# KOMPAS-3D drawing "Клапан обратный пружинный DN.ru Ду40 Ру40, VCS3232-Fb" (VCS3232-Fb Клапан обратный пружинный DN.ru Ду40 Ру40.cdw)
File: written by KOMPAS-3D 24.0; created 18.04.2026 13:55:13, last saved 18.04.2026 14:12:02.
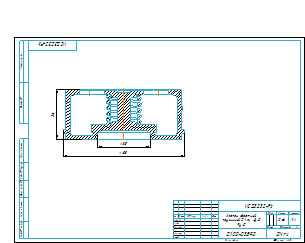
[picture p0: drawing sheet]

Document properties: c3d_UniqueCompID: 071bd168-1a06-425c-849c-e99e84a96128; Наименование: Деталь; Автор: 712; Класс точности: c; Знак неуказанной шероховатости: Шероховатость не задана; Рассекать на разрезах: Да; c3d_UniqueCompID: 071bd168-1a06-425c-849c-e99e84a96128; Наименование: Деталь; Автор: 712; Класс точности: c; Знак неуказанной шероховатости: Шероховатость не задана; Рассекать на разрезах: Да; c3d_UniqueCompID: 071bd168-1a06-425c-849c-e99e84a96128; Наименование: Деталь; Автор: 712; Класс точности: c; Знак неуказанной шероховатости: Шероховатость не задана; Рассекать на разрезах: Да; c3d_UniqueCompID: 071bd168-1a06-425c-849c-e99e84a96128; Наименование: Деталь; Автор: 712; Класс точности: c; Знак неуказанной шероховатости: Шероховатость не задана; Рассекать на разрезах: Да; c3d_UniqueCompID: 071bd168-1a06-425c-849c-e99e84a96128; Наименование: Деталь; Автор: 712; Класс точности: c; Знак неуказанной шероховатости: Шероховатость не задана; Рассекать на разрезах: Да; Автор: 712; Форматы листов документа: A3; Полное имя файла: VCS3232-Fb Клапан обратный пружинный DN.ru Ду40 Ру40.m3d; Масса: 0.61; Наименование: Клапан обратный пружинный DN.ru Ду40 Ру40; Количество листов документа: 1; Примечание: D100-03890

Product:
- Body: Тело 1  | qty 1
    Масса: 0.509779
- Part/product: Клапан обратный пружинный DN.ru Ду40 Ру40  | designation VCS3232-Fb
    Масса: 0.61
    Раздел спецификации: Прочие изделия
    Примечание: D100-03890
    additional columns: 071bd168-1a06-425c-849c-e99e84a96128; Деталь; 712; c; Шероховатость не задана; Да

Views: Вид 1, Местный разрез 1, Спереди
Referenced files in C:\Users\712\Desktop\Новая папка (4)\: VCS3232-Fb Клапан обратный пружинный DN.ru Ду15 Ру40.m3d, VCS3232-Fb Клапан обратный пружинный DN.ru Ду40 Ру40.m3d, VCS3232-Fb Клапан обратный пружинный DN.ru Ду15 Ру40.cdw
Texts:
  VCS3232-Fb
  Клапан обратный
  пружинный DN.ru Ду40
  Ру40
  Клапан обратный пружинный DN.ru Ду40 Ру40
  VCS3232-Fb Клапан обратный пружинный DN.ru Ду40 Ру40
Dimensions and other numbers on the sheet: 0; 3; 2; 4; 88; 38; 36; 2:1; 1; 0,61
